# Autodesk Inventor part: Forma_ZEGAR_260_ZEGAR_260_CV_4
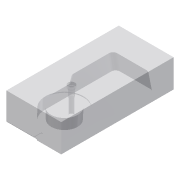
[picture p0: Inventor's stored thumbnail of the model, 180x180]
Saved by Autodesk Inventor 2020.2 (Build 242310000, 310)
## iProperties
Created: 2015-01
Part Number: Forma_ZEGAR_260_ZEGAR_260_CV_4
Material: Ogólny
Document SubType Name: Modeling
Designer: F.Stasiak
Density: 1 g/cm^3
Appearance: Domyślna
Catalog Web Link: www.expertbooks.pl
Manager: www.cadconsulting.pl
Company: Fabian Stasiak CAD Consulting
Author: F.Stasiak
Subject: Zbiór ćwiczeń. Autodesk Inventor 2020. Kurs Professional
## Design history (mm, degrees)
node "Forma_ZEGAR_260_ZEGAR_260_CV_Base"
feature "Rzeźbienie3"
feature "Bryła5::Forma_ZEGAR_260_ZEGAR_260_CV_Base"
tag "Bryła wyprowadzona1"
node "Bryła1"
feature "Forma_ZEGAR_260_ZEGAR_260_CV_Base_Bodies"
feature "Powierzchnia3"
body "Srf3"
